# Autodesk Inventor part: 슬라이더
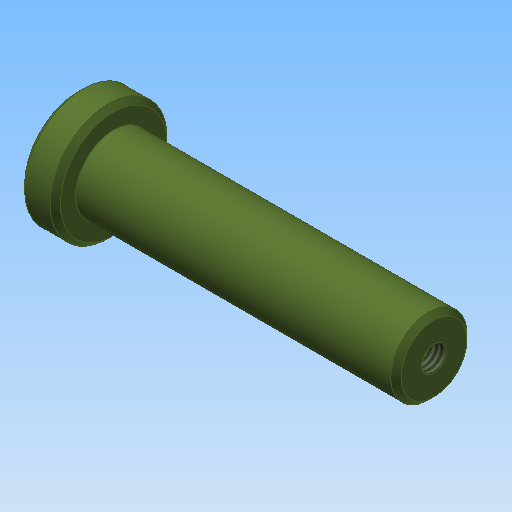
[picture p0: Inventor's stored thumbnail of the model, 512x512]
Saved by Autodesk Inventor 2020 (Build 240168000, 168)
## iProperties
Created: 2011-04
Part Number: 슬라이더
Document SubType Name: Modeling
Density: 1 g/cm^3
Material: 일반
Appearance: 올리브 녹색
Author: pww
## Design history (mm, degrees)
sketch "스케치1"
  geometry: L1 (-7, 0)-(63, 0); L2 (63, 0)-(63, 7.5); L3 (63, 7.5)-(0, 7.5); L4 (-7, 0)-(-7, 11.5); L5 (-7, 11.5)-(0, 11.5); L6 (0, 11.5)-(0, 7.5); 1 further point
  constraints: 12 end point, 3 perpendicular, 2 horizontal, 2 point on line, 1 parallel
  dimensions: "d1" = 70 distance of L1.start L1.end; "d19" = 15 diameter of L3 L1; "d20" = 7 distance of L4.end L5.end; "d21" = 23 diameter of L5 L1
revolve "회전1" stored, may be unused: angle "d4" = 90 deg
chamfer "모따기1" distance "d16" = 1; stored, may be unused: second distance "d17" = 2, angle "d18" = 45 deg
hole "구멍2" diameter "d24" = 4.917; stored, may be unused: countersink angle "d28" = 90 deg, drill point angle "d30" = 118 deg; dims "d22" = 10, "d23" = 10, "d25" = 10, "d26" = 4, "d27" = 2, "d29" = 13
node "솔리드1"
